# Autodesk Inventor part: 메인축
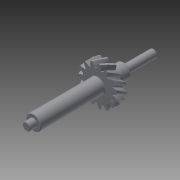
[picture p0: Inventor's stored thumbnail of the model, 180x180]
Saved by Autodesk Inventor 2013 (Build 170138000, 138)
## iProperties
Created: 2016-12
Part Number: 메인축
Material: 강철, 탄소
Document SubType Name: Modeling
Designer: mduedu
Categories: <?xml version="1.0" encoding="UTF-16"?> <MemberInstance><Categories><FamilyTemplate><FamilyTemplateParameter ValueType="xs:double" Id="1" ObjectReferenceKey="da
Density: 1 g/cm^3
CustomPartVersion: 1
Author: mduedu
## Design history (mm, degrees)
sketch "Sketch1"
  geometry: C1 r 19.321 at (0, 0)
  constraints: 1 centre point
  dimensions: "d0" = 38.64102 diameter of C1 (= da_da)
extrude "Extrusion1" new body sketch "Sketch1" distance "d1" = 10 (= da_b); taper "d2" = 0 deg
workplane "Work Plane2"
sketch "Sketch2"
  geometry: C1 r 19.321 at (0, 0) reference; C2 r 17.321 at (0, 0)
  constraints: 1 centre point, 1 coincident
  dimensions: "d3" = 34.64102 diameter of C2 (= da_dw)
feature "피치 지름" sketch "Sketch2" dims "d4" = 10, "d5" = 0
workplane "Work Plane8"
workplane "Work Plane9"
feature "스퍼 기어" dims "da_b" = 10, "da_d" = 34.64102, "da_aw" = 43.87862, "da_da" = 38.64102, "da_df" = 29.64102, "da_dw" = 34.64102, angle "da_beta" = 30 deg, "da_lefttooth" = 0, "da_righttooth" = 10
sketch "스케치3"
  geometry: C1 r 7.5 at (0, 0); 1 further point
  constraints: 1 centre point, 1 coincident
  dimensions: "d49" = 15 diameter of C1
extrude "돌출2" join sketch "스케치3" distance "d50" = 64; taper "d51" = 0 deg
sketch "스케치4"
  geometry: C1 r 4 at (0, 0); 1 further point
  constraints: 1 centre point, 1 coincident
  dimensions: "d52" = 8 diameter of C1
extrude "돌출3" join sketch "스케치4" distance "d53" = 7; taper "d54" = 0 deg
sketch "스케치5"
  geometry: C1 r 7.5 at (0, 0) reference; 1 further point
extrude "돌출4" join sketch "스케치5" distance "d55" = 16; taper "d56" = 0 deg
sketch "스케치6"
  geometry: C1 r 4 at (0, 0); 1 further point
  constraints: 1 centre point, 1 coincident
  dimensions: "d57" = 8 diameter of C1
extrude "돌출5" join sketch "스케치6" distance "d58" = 30; taper "d59" = 0 deg
chamfer "모따기1" distance "d60" = 0.5; stored, may be unused: second distance "d61" = 2, angle "d62" = 45 deg
fillet "모깎기1" dims "d63" = 0.5
body "Solid1"
body "Srf1"
other parameters: "d16" = 43.87862 (= da_aw), "d17" = 0, "d34" = 12 deg (computed from da_z), "d39" = 0, "d41" = 0, "d43" = 43.87862 (= da_aw), "d46" = 43.87862 (= da_aw), "d47" = 0, "d48" = 0
